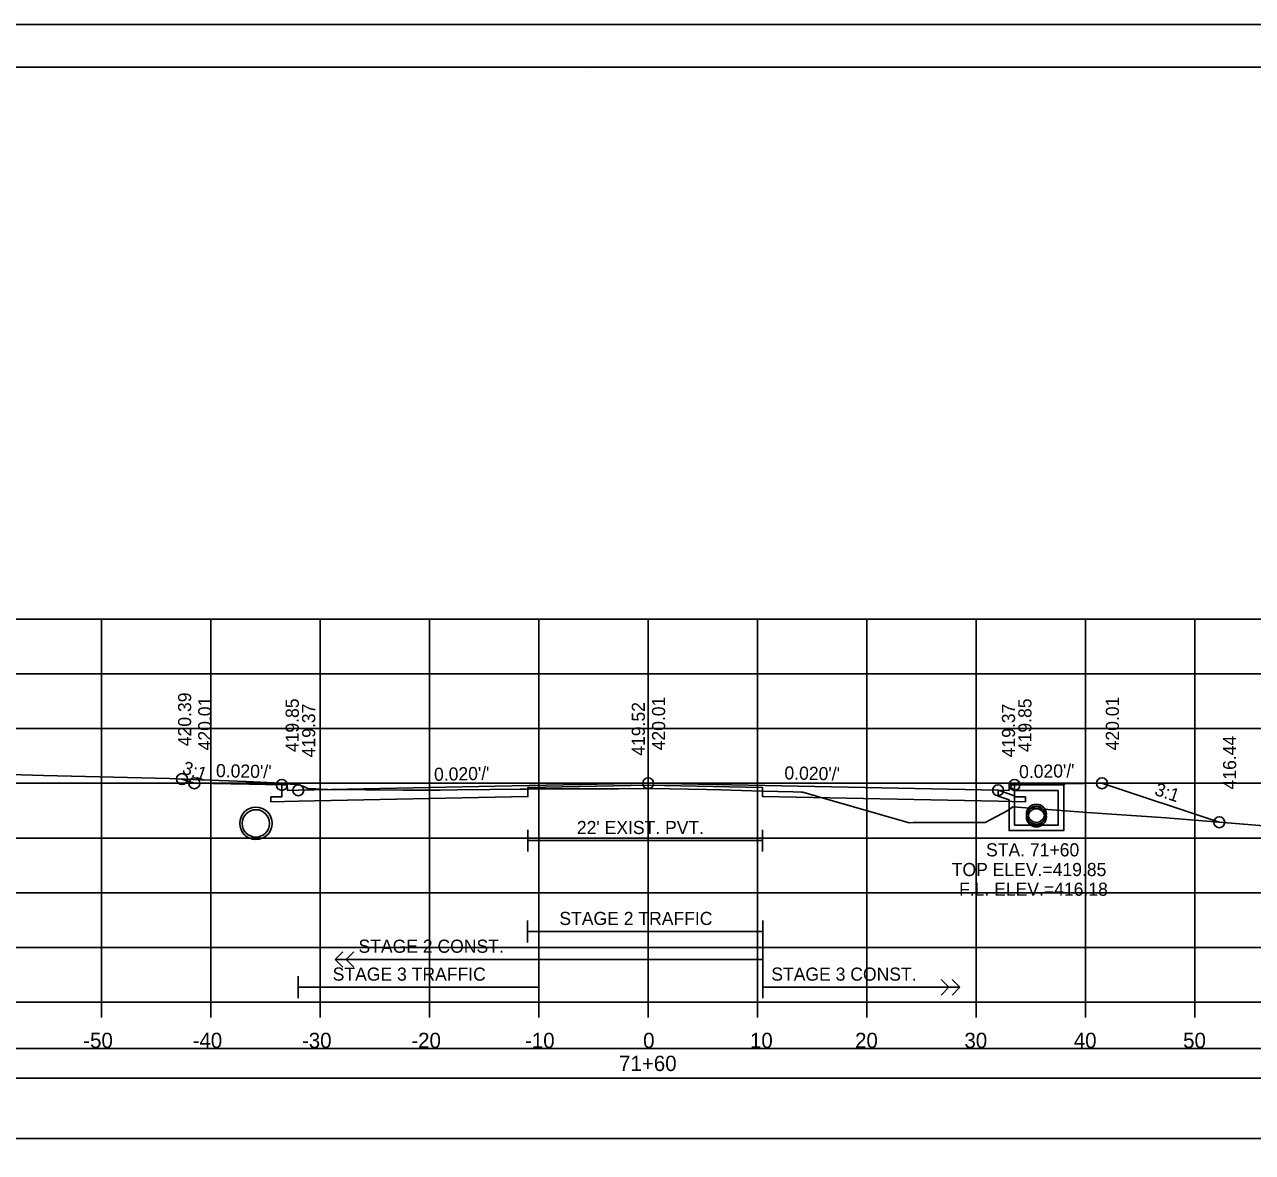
# Model space of a CAD drawing. Extents: x 1371057 to 1372761, y 380005 to 390517.
# Drawn here: x 1371170.5 to 1371282.8, y 386515.5 to 386618.6 of the extents above; entities that cross this region are included whole.
import ezdxf

# ---------------------------------------------------------------- set-up
doc = ezdxf.new("R2010")
doc.units = 0
for name, color, linetype in [('R_Alt Surface', 7, 'Continuous'), ('R_Axis', 7, 'Continuous'), ('R_Axis Annot', 7, 'Continuous'), ('R_Border', 7, 'Continuous'), ('R_Detour', 7, 'Continuous'), ('R_Dimension', 7, 'Continuous'), ('R_Exist Surface', 7, 'Continuous'), ('R_Fin Surface', 7, 'Continuous'), ('R_Grid', 7, 'Continuous'), ('R_No Plot', 7, 'Continuous'), ('R_Striping', 7, 'Continuous'), ('R_Water', 7, 'Continuous'), ('R_Water Annot', 7, 'Continuous'), ('R_Xsect Elev', 7, 'Continuous'), ('R_Xsect Slope', 7, 'Continuous')]:
    doc.layers.add(name, color=color, linetype=linetype)

msp = doc.modelspace()

# ---------------------------------------------------------------- linework, layer by layer
at = {"layer": 'R_Alt Surface'}
for points in [[(1371261.03, 386549.05), (1371261.03, 386547.97), (1371262.03, 386547.95), (1371262.03, 386547.52), (1371259.53, 386547.57), (1371237.98, 386548), (1371237.98, 386548.83), (1371227.53, 386549.04), (1371216.53, 386548.82), (1371216.53, 386547.99), (1371195.53, 386547.57), (1371193.03, 386547.52), (1371193.03, 386547.95), (1371194.03, 386547.97), (1371194.03, 386549.05)], [(1371216.53, 386544.96), (1371216.53, 386542.96)], [(1371216.53, 386543.96), (1371237.98, 386543.96)], [(1371237.98, 386544.96), (1371237.98, 386542.96)]]:
    msp.add_lwpolyline(points, dxfattribs=at)
at = {"layer": 'R_Axis'}
for p, q in [((1371077.53, 386529.2), (1371377.53, 386529.2)), ((1371177.53, 386527.8), (1371177.53, 386529.2)), ((1371187.53, 386527.8), (1371187.53, 386529.2)), ((1371197.53, 386527.8), (1371197.53, 386529.2)), ((1371207.53, 386527.8), (1371207.53, 386529.2)), ((1371217.53, 386527.8), (1371217.53, 386529.2)), ((1371227.53, 386527.8), (1371227.53, 386529.2)), ((1371237.53, 386527.8), (1371237.53, 386529.2)), ((1371247.53, 386527.8), (1371247.53, 386529.2)), ((1371257.53, 386527.8), (1371257.53, 386529.2)), ((1371267.53, 386527.8), (1371267.53, 386529.2)), ((1371277.53, 386527.8), (1371277.53, 386529.2))]:
    msp.add_line(p, q, dxfattribs=at)
at = {"layer": 'R_Border'}
for p, q in [((1371069.53, 386614.66), (1371385.71, 386614.66)), ((1371222.05, 386614.4), (1371222.05, 386614.4)), ((1371222.05, 386614.4), (1371222.05, 386614.4))]:
    msp.add_line(p, q, dxfattribs=at)
at = {"layer": 'R_Detour'}
msp.add_lwpolyline([(1371074.38, 386522.25), (1371380.69, 386522.25), (1371380.69, 386524.95), (1371074.38, 386524.95)], close=True, dxfattribs=at)
at = {"layer": 'R_Dimension'}
msp.add_lwpolyline([(1371074.38, 386516.72), (1371380.69, 386516.72), (1371380.69, 386522.25), (1371074.38, 386522.25)], close=True, dxfattribs=at)
at = {"layer": 'R_Exist Surface'}
msp.add_lwpolyline([(1371169.19, 386550.02), (1371172.24, 386549.91), (1371183.75, 386549.63), (1371186.66, 386549.53), (1371190.79, 386549.37), (1371191.44, 386549.35), (1371193.32, 386549.25), (1371195.19, 386549.09), (1371195.6, 386549.06), (1371196.09, 386548.88), (1371196.47, 386548.7), (1371197.13, 386548.7), (1371197.78, 386548.65), (1371198.23, 386548.65), (1371205.11, 386548.57), (1371208.52, 386548.58), (1371210.06, 386548.6), (1371213.09, 386548.63), (1371215.83, 386548.67), (1371216.53, 386548.68), (1371216.62, 386548.69), (1371224.82, 386548.71), (1371227.25, 386548.72), (1371227.25, 386548.72), (1371227.25, 386548.72), (1371227.72, 386548.72), (1371227.9, 386548.72), (1371232.85, 386548.63), (1371234.21, 386548.6), (1371235.09, 386548.57), (1371237.98, 386548.48), (1371240.8, 386548.42), (1371241.52, 386548.4), (1371241.66, 386548.38), (1371243.43, 386547.86), (1371251.4, 386545.6), (1371251.75, 386545.61), (1371258.34, 386545.62), (1371260.42, 386546.72), (1371260.87, 386547.04), (1371267.69, 386546.54), (1371274.9, 386546.03), (1371284.59, 386545.24)], dxfattribs=at)
at = {"layer": 'R_Fin Surface'}
msp.add_lwpolyline([(1371184.9, 386549.59), (1371186.03, 386549.21), (1371191.03, 386549.11), (1371194.03, 386549.05), (1371194.53, 386549.05), (1371194.54, 386548.55), (1371195.53, 386548.57), (1371195.53, 386548.57), (1371213.53, 386548.93), (1371227.53, 386549.21), (1371227.53, 386549.21), (1371259.53, 386548.57), (1371260.53, 386548.55), (1371260.53, 386549.05), (1371260.81, 386549.05), (1371261.03, 386549.05), (1371264.03, 386549.11), (1371269.03, 386549.21), (1371279.75, 386545.64)], dxfattribs=at)
at = {"layer": 'R_Grid'}
for p, q in [((1371077.53, 386564.2), (1371377.53, 386564.2)), ((1371177.53, 386529.2), (1371177.53, 386564.2)), ((1371187.53, 386529.2), (1371187.53, 386564.2)), ((1371197.53, 386529.2), (1371197.53, 386564.2)), ((1371207.53, 386529.2), (1371207.53, 386564.2)), ((1371217.53, 386529.2), (1371217.53, 386564.2)), ((1371227.53, 386529.2), (1371227.53, 386564.2)), ((1371237.53, 386529.2), (1371237.53, 386564.2)), ((1371247.53, 386529.2), (1371247.53, 386564.2)), ((1371257.53, 386529.2), (1371257.53, 386564.2)), ((1371267.53, 386529.2), (1371267.53, 386564.2)), ((1371277.53, 386529.2), (1371277.53, 386564.2)), ((1371077.53, 386559.2), (1371377.53, 386559.2)), ((1371077.53, 386554.2), (1371377.53, 386554.2)), ((1371077.53, 386549.2), (1371377.53, 386549.2)), ((1371077.53, 386544.2), (1371377.53, 386544.2)), ((1371077.53, 386539.2), (1371377.53, 386539.2)), ((1371077.53, 386534.2), (1371377.53, 386534.2)), ((1371077.53, 386529.2), (1371377.53, 386529.2))]:
    msp.add_line(p, q, dxfattribs=at)
at = {"layer": 'R_No Plot'}
msp.add_line((1371057.13, 386618.55), (1371390.46, 386618.55), dxfattribs=at)
for points in [[(1371057.12, 386618.55), (1371390.46, 386618.55), (1371390.46, 386405.22), (1371057.12, 386405.22)], [(1371303.45, 386614.66), (1371323.07, 386614.66), (1371323.07, 386604.78), (1371339.18, 386604.78), (1371362.38, 386604.78), (1371362.5, 386576.62), (1371385.71, 386576.62), (1371385.71, 386409.2), (1371069.53, 386409.2), (1371069.53, 386614.66)]]:
    msp.add_lwpolyline(points, close=True, dxfattribs=at)
for centre, radius in [((1371184.9, 386549.59), 0.5), ((1371186.03, 386549.21), 0.5), ((1371194.03, 386549.05), 0.5), ((1371227.53, 386549.21), 0.5), ((1371261.03, 386549.05), 0.5), ((1371269.03, 386549.21), 0.5), ((1371195.53, 386548.57), 0.5), ((1371259.53, 386548.57), 0.5), ((1371263.03, 386546.38), 0.917), ((1371191.66, 386545.54), 1.48), ((1371263.03, 386546.13), 0.917), ((1371279.75, 386545.64), 0.5)]:
    msp.add_circle(centre, radius, dxfattribs=at)
at = {"layer": 'R_Striping'}
for p, q in [((1371216.48, 386536.65), (1371216.48, 386534.65)), ((1371238.03, 386536.65), (1371238.03, 386529.56)), ((1371216.48, 386535.65), (1371238.03, 386535.65)), ((1371198.91, 386533.11), (1371199.62, 386533.81)), ((1371199.91, 386533.11), (1371200.62, 386533.81)), ((1371198.91, 386533.11), (1371238.03, 386533.11)), ((1371199.62, 386532.4), (1371198.91, 386533.11)), ((1371200.62, 386532.4), (1371199.91, 386533.11)), ((1371195.53, 386531.56), (1371195.53, 386529.56)), ((1371217.53, 386531.56), (1371217.53, 386529.56)), ((1371217.53, 386530.56), (1371195.53, 386530.56)), ((1371238.03, 386530.56), (1371256.03, 386530.56)), ((1371238.07, 386530.56), (1371248.07, 386530.56)), ((1371255.03, 386530.56), (1371254.33, 386531.27)), ((1371254.33, 386529.85), (1371255.03, 386530.56)), ((1371256.03, 386530.56), (1371255.33, 386531.27)), ((1371255.33, 386529.85), (1371256.03, 386530.56))]:
    msp.add_line(p, q, dxfattribs=at)
at = {"layer": 'R_Water'}
for p, q in [((1371259.53, 386548.57), (1371261.03, 386548.05)), ((1371260.7, 386548.88), (1371260.78, 386549.05)), ((1371260.7, 386548.88), (1371261.03, 386548.55)), ((1371265.53, 386549.05), (1371260.78, 386549.05)), ((1371265.03, 386548.55), (1371261.03, 386548.55)), ((1371265.03, 386547.55), (1371265.03, 386548.55)), ((1371265.53, 386547.55), (1371265.53, 386549.05)), ((1371259.53, 386548.04), (1371260.53, 386547.69)), ((1371260.53, 386547.55), (1371260.53, 386547.69)), ((1371261.03, 386547.55), (1371261.03, 386548.05))]:
    msp.add_line(p, q, dxfattribs=at)
for points in [[(1371259.53, 386548.04), (1371259.53, 386548.57)], [(1371265.53, 386547.55), (1371265.53, 386544.88), (1371263.03, 386544.88), (1371260.53, 386544.88), (1371260.53, 386547.55)], [(1371265.03, 386547.55), (1371265.03, 386545.38), (1371263.03, 386545.38), (1371261.03, 386545.38), (1371261.03, 386547.55)]]:
    msp.add_lwpolyline(points, dxfattribs=at)
for centre, radius in [((1371191.66, 386545.54), 1.25), ((1371263.03, 386546.38), 0.75), ((1371263.03, 386546.13), 0.75)]:
    msp.add_circle(centre, radius, dxfattribs=at)
at = {"layer": 'R_Xsect Elev'}
msp.add_line((1371227.53, 386548.72), (1371227.53, 386558.72), dxfattribs=at)

# ---------------------------------------------------------------- texts
at = {"layer": 'R_Axis Annot'}
for s, p in [('-50', (1371175.87, 386525)), ('-40', (1371185.87, 386525)), ('-30', (1371195.87, 386525)), ('-20', (1371205.87, 386525)), ('-10', (1371216.27, 386525)), ('0', (1371227.07, 386525)), ('10', (1371236.84, 386525)), ('20', (1371246.45, 386525)), ('30', (1371256.45, 386525)), ('40', (1371266.45, 386525)), ('50', (1371276.45, 386525)), ('71+60', (1371224.87, 386522.9))]:
    msp.add_text(s, height=1.4, dxfattribs=at).set_placement(p)
at = {"layer": 'R_Striping'}
for s, p in [('STAGE 2 TRAFFIC', (1371219.41, 386536.25)), ('STAGE 2 CONST.', (1371201.04, 386533.71)), ('STAGE 3 TRAFFIC', (1371198.68, 386531.16)), ('STAGE 3 CONST.', (1371238.79, 386531.16))]:
    msp.add_text(s, height=1.2, dxfattribs=at).set_placement(p)
at = {"layer": 'R_Water'}
msp.add_text("22' EXIST. PVT.", height=1.2, dxfattribs=at).set_placement((1371221.01, 386544.56))
at = {"layer": 'R_Water Annot'}
for s, p in [('STA. 71+60', (1371258.43, 386542.52)), ('TOP ELEV.=419.85', (1371255.29, 386540.72)), ('F.L. ELEV.=416.18', (1371255.96, 386538.92))]:
    msp.add_text(s, height=1.2, dxfattribs=at).set_placement(p)
at = {"layer": 'R_Xsect Elev'}
for s, p in [('420.39', (1371185.74, 386552.59)), ('420.01', (1371187.58, 386552.21)), ('419.85', (1371195.58, 386552.05)), ('419.37', (1371197.08, 386551.57)), ('419.52', (1371227.23, 386551.72)), ('420.01', (1371229.08, 386552.21)), ('419.37', (1371261.08, 386551.57)), ('419.85', (1371262.58, 386552.05)), ('420.01', (1371270.58, 386552.21)), ('416.44', (1371281.3, 386548.64))]:
    msp.add_text(s, height=1.2, rotation=90, dxfattribs=at).set_placement(p)
at = {"layer": 'R_Xsect Slope'}
for s, rotation, p in [('3:1', 341.5624, (1371184.83, 386550.13)), ("0.020'/'", 358.8542, (1371188, 386549.77)), ("0.020'/'", 1.1458, (1371207.96, 386549.42)), ("0.020'/'", 358.8543, (1371239.98, 386549.56)), ("0.020'/'", 1.1458, (1371261.46, 386549.66)), ('3:1', 341.567, (1371273.76, 386548.16))]:
    msp.add_text(s, height=1.2, rotation=rotation, dxfattribs=at).set_placement(p)

doc.saveas('drawing.dxf')
